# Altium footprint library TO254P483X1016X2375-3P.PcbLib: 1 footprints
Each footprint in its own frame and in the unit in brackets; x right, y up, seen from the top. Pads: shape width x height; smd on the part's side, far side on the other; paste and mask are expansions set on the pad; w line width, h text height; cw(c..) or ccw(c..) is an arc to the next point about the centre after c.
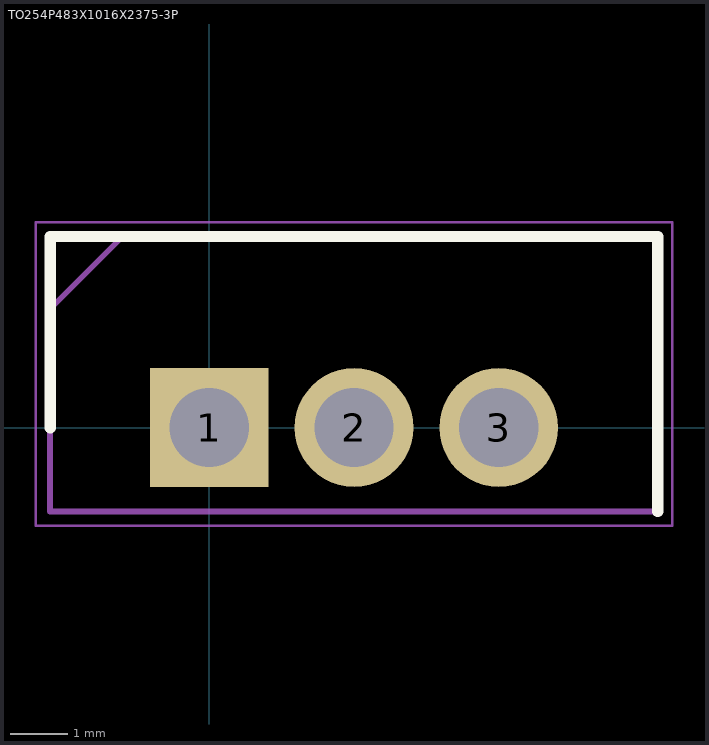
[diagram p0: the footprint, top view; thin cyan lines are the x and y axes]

## TO254P483X1016X2375-3P [mm]
pads (3):
  rect 2.085x2.085 / inner round 2.085 / far side rect 2.085x2.085 hole 1.39: 1(0,0)
  round 2.085 hole 1.39: 2(2.54,0) 3(5.08,0)
Top Overlay:
  lines w0.2: -2.794,0 -2.794,3.353 7.874,3.353 7.874,-1.473
Mechanical 15:
  lines w0.1: -2.794,2.083 -1.524,3.353 ; -2.794,-1.473 7.874,-1.473 7.874,3.353 -2.794,3.353 -2.794,-1.473
Mechanical 20:
  lines w0.05: -3.044,-1.723 8.124,-1.723 8.124,3.603 -3.044,3.603 -3.044,-1.723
